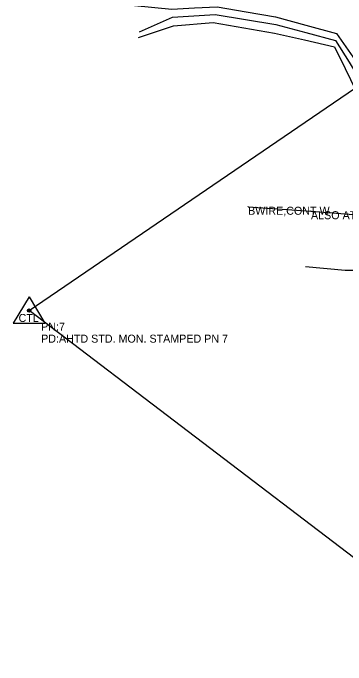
# Model space of a CAD drawing. Extents: x 997398 to 1003416, y 334596 to 337085.
# Drawn here: x 998954.3 to 999162, y 335651.1 to 336058.3 of the extents above; entities that cross this region are included whole.
import ezdxf

# ---------------------------------------------------------------- set-up
doc = ezdxf.new("R2010")
doc.units = 0
for name, color, linetype in [('Default', 7, 'Continuous'), ('S_CURB', 7, 'Continuous'), ('S_FENCE', 7, 'Continuous'), ('S_FENCE_ANNOT', 7, 'Continuous'), ('S_MSC_PT_SYM', 7, 'Continuous'), ('S_PRIMARY_CTL', 7, 'Continuous'), ('S_PRIMARY_CTL_ANNOT', 7, 'Continuous'), ('S_STREAM', 7, 'Continuous')]:
    doc.layers.add(name, color=color, linetype=linetype)

msp = doc.modelspace()

# ---------------------------------------------------------------- linework, layer by layer
at = {"layer": 'Default'}
for p, q in [((998964.3, 335872.43), (999557.02, 336277.74)), ((999254.77, 335651.12), (998964.3, 335872.43))]:
    msp.add_line(p, q, dxfattribs=at)
at = {"layer": 'S_CURB'}
msp.add_lwpolyline([(999228.98, 335884.91), (999224.1, 335891.55), (999210.78, 335898.41), (999198.87, 335897.27), (999180.22, 335897.42), (999161.56, 335897.57), (999136.81, 335899.76)], dxfattribs=at)
at = {"layer": 'S_FENCE'}
for p, q in [((999100.97, 335937.31), (999140.23, 335934.52)), ((999140.23, 335934.52), (999187.31, 335930.69))]:
    msp.add_line(p, q, dxfattribs=at)
at = {"layer": 'S_MSC_PT_SYM'}
for points in [[(999100.97, 335937.31), (999100.97, 335937.36), (999100.97, 335937.31), (999100.92, 335937.31), (999100.97, 335937.31), (999100.97, 335937.26), (999100.97, 335937.31), (999101.02, 335937.31)], [(999140.23, 335934.52), (999140.23, 335934.57), (999140.23, 335934.52), (999140.18, 335934.52), (999140.23, 335934.52), (999140.23, 335934.47), (999140.23, 335934.52), (999140.28, 335934.52)]]:
    msp.add_lwpolyline(points, dxfattribs=at)
at = {"layer": 'S_PRIMARY_CTL'}
for p, q in [((998964.3, 335881.13), (998954.27, 335864.61)), ((998964.3, 335881.13), (998974.13, 335864.61)), ((998954.27, 335864.61), (998974.13, 335864.61))]:
    msp.add_line(p, q, dxfattribs=at)
for radius in [1.04, 0.609, 0.344]:
    msp.add_circle((998964.3, 335872.43), radius, dxfattribs=at)
at = {"layer": 'S_STREAM'}
for points in [[(999030.13, 336063.09), (999053.42, 336060.79), (999067.52, 336061.49), (999081.61, 336062.19), (999099.8, 336059.05), (999117.99, 336055.9), (999137.08, 336050.73), (999156.18, 336045.56), (999166.41, 336030.96), (999176.64, 336016.36), (999183.48, 336004.74), (999190.31, 335993.12), (999199.28, 335979.3), (999208.26, 335965.48), (999220.04, 335959.33), (999231.82, 335953.19), (999242.01, 335943.09), (999252.2, 335933)], [(999033.16, 336046.63), (999053.76, 336055.67), (999067.05, 336056.56), (999080.34, 336057.45), (999099.29, 336054.26), (999118.25, 336051.08), (999136.92, 336046.13), (999155.59, 336041.18), (999164, 336027.57), (999172.4, 336013.96), (999177.91, 335998.7), (999183.41, 335983.44), (999195.03, 335972.3), (999206.65, 335961.17), (999218.82, 335955.75), (999230.99, 335950.32), (999238.91, 335940.58), (999246.82, 335930.83)], [(999032.67, 336043), (999054.31, 336050.3), (999079.17, 336052.39), (999098.35, 336049.09), (999117.52, 336045.79), (999136.22, 336041.52), (999154.92, 336037.25), (999161.55, 336023.58), (999168.19, 336009.91), (999174.56, 335996.03), (999180.94, 335982.15), (999192.97, 335970.09), (999205.01, 335958.03), (999217.24, 335953.12), (999229.46, 335948.22), (999242.79, 335929)]]:
    msp.add_lwpolyline(points, dxfattribs=at)

# ---------------------------------------------------------------- texts
at = {"layer": 'S_FENCE_ANNOT'}
for s, p in [('BWIRE,CONT W', (999100.97, 335932.31)), ('ALSO AT TREELINE', (999140.23, 335929.52))]:
    msp.add_text(s, height=5, dxfattribs=at).set_placement(p)
at = {"layer": 'S_PRIMARY_CTL'}
msp.add_text('CTL', height=5, rotation=360, dxfattribs=at).set_placement((998957.72, 335865.35))
at = {"layer": 'S_PRIMARY_CTL_ANNOT'}
for s, p in [('PN:7', (998971.8, 335859.93)), ('PD:AHTD STD. MON. STAMPED PN 7', (998971.8, 335852.43))]:
    msp.add_text(s, height=5, dxfattribs=at).set_placement(p)

doc.saveas('drawing.dxf')
